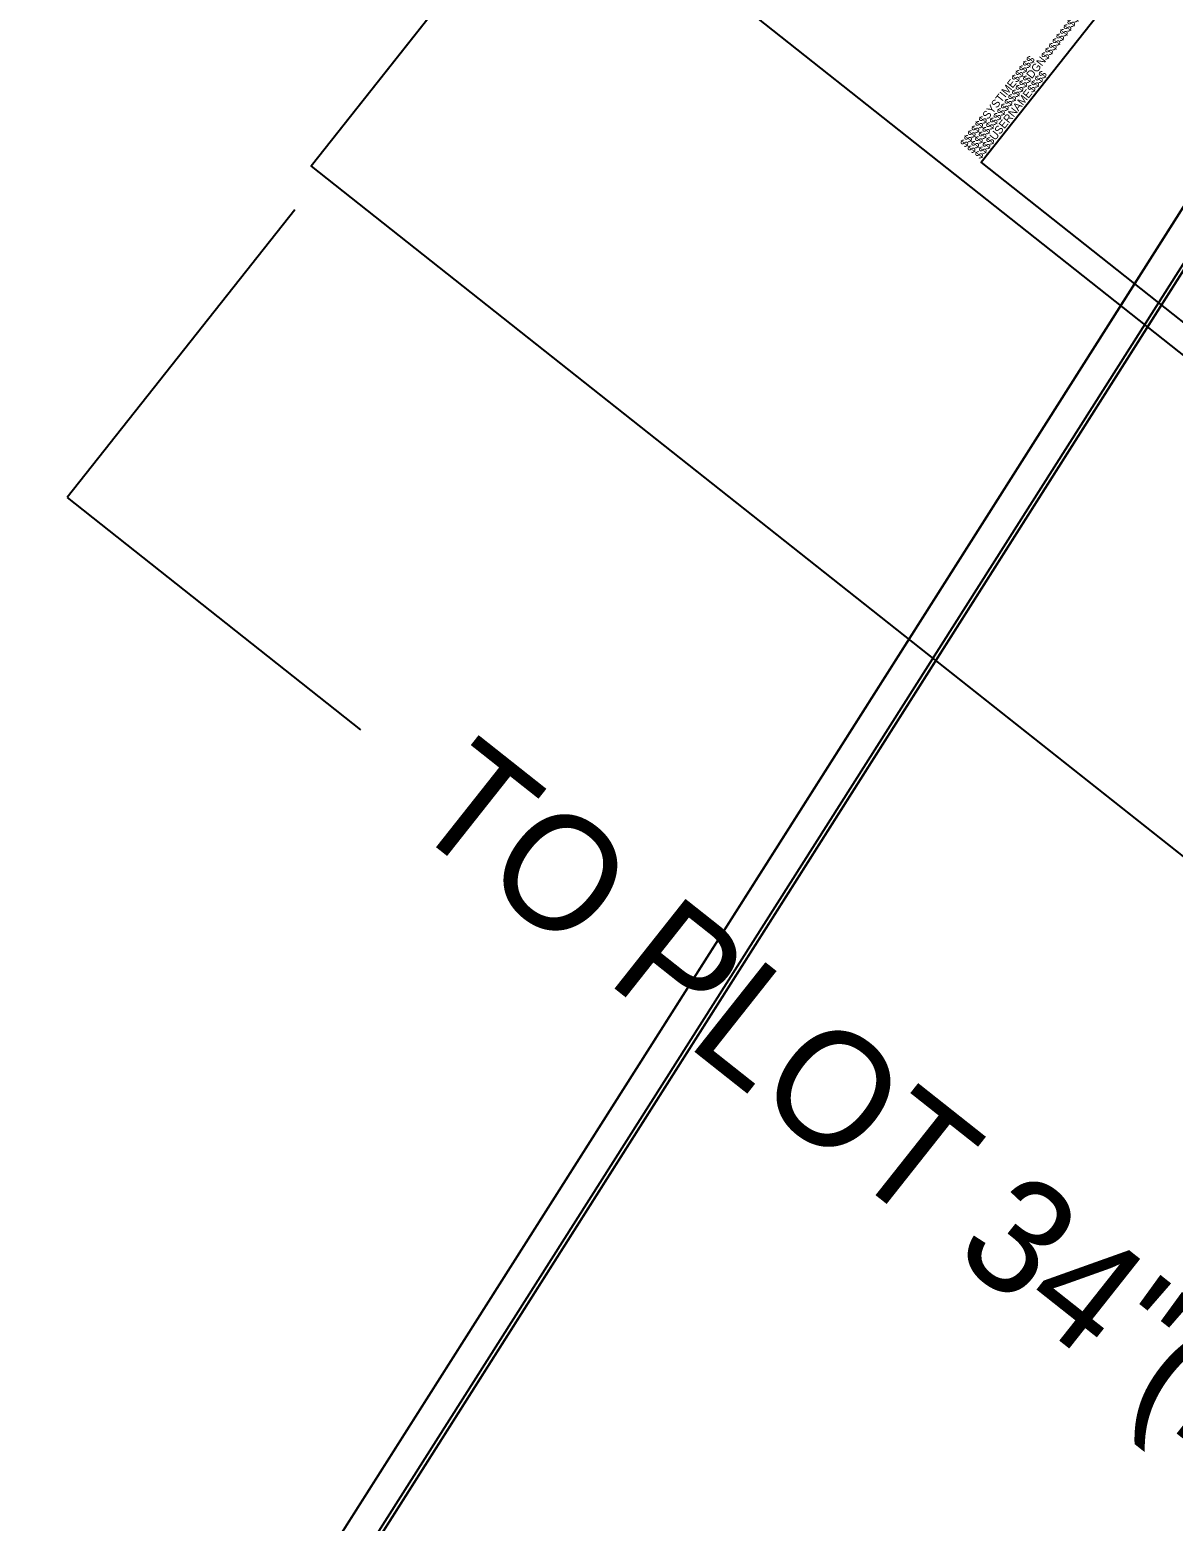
# Model space of a CAD drawing. Extents: x 1778994 to 1784559, y 810461 to 816654.
# Drawn here: x 1780200 to 1780950, y 812239 to 813217 of the extents above; entities that cross this region are included whole.
import ezdxf

# ---------------------------------------------------------------- set-up
doc = ezdxf.new("R2010")
doc.units = 0
for name, color, linetype in [('Sheet Clip Boundary CELL', 7, 'Continuous'), ('Sheet Cutting Line CELL', 7, 'Continuous'), ('Sheet Detail CELL', 7, 'Continuous'), ('Sheet Layout Plan Border', 7, 'Continuous'), ('Sheet Plan CELL', 7, 'Continuous'), ('Sheet Plan Layout CELL', 7, 'Continuous'), ('Sheet Plot Border Inside CELL', 7, 'Continuous'), ('Sheet Plot Border Outside CELL', 7, 'Continuous')]:
    doc.layers.add(name, color=color, linetype=linetype)

msp = doc.modelspace()

# ---------------------------------------------------------------- linework, layer by layer
at = {"layer": 'Sheet Clip Boundary CELL'}
msp.add_lwpolyline([(1781004.66, 813135.18), (1780254.51, 811953.1), (1780962.49, 811503.81), (1781063.9, 811663.61), (1781242.47, 811550.29), (1781891.21, 812572.57)], close=True, dxfattribs=at)
at = {"layer": 'Sheet Cutting Line CELL'}
for p, q in [((1781749.66, 814852.38), (1780384.09, 813127.55)), ((1781101.65, 813330.03), (1780199.6, 811908.59)), ((1780384.09, 813127.55), (1783024.7, 811036.95))]:
    msp.add_line(p, q, dxfattribs=at)
at = {"layer": 'Sheet Detail CELL'}
for p, q in [((1780373.43, 813098.94), (1780223.99, 812910.19)), ((1780223.99, 812910.19), (1780416.55, 812757.74))]:
    msp.add_line(p, q, dxfattribs=at)
msp.add_lwpolyline([(1781847.91, 814423.9), (1784200, 812561.73), (1783175.8, 811268.08), (1780823.71, 813130.25)], close=True, dxfattribs=at)
msp.add_lwpolyline([(1780853.12, 813106.97), (1780853.12, 813106.97)], dxfattribs=at)
at = {"layer": 'Sheet Layout Plan Border'}
msp.add_lwpolyline([(1781004.66, 813135.18), (1780254.51, 811953.1), (1780962.49, 811503.81), (1781063.9, 811663.61), (1781242.47, 811550.29), (1781891.21, 812572.57)], close=True, dxfattribs=at)
at = {"layer": 'Sheet Plan CELL'}
for points in [[(1781114.25, 811348.25), (1781918, 812614.78), (1781031.45, 813177.39), (1780227.72, 811910.89)], [(1781031.45, 813177.39), (1781917.99, 812614.82), (1781221.47, 811517.18), (1781094.76, 811597.57), (1780987.56, 811428.68), (1780227.72, 811910.89)]]:
    msp.add_lwpolyline(points, close=True, dxfattribs=at)
at = {"layer": 'Sheet Plan Layout CELL'}
msp.add_lwpolyline([(1781917.99, 812614.82), (1781031.45, 813177.39), (1780227.72, 811910.9), (1780935.71, 811461.6), (1781063.9, 811663.61), (1781242.47, 811550.29)], close=True, dxfattribs=at)
at = {"layer": 'Sheet Plot Border Inside CELL'}
for points in [[(1784230.15, 812559.54), (1781642.85, 814607.93), (1780597.55, 813287.62), (1783184.85, 811239.23)], [(1781111.57, 813308.33), (1780218.91, 811901.68), (1781109.67, 811336.39), (1782002.34, 812743.04)]]:
    msp.add_lwpolyline(points, close=True, dxfattribs=at)
at = {"layer": 'Sheet Plot Border Outside CELL'}
for points in [[(1784390.27, 812761.78), (1781749.66, 814852.38), (1780384.09, 813127.55), (1783024.7, 811036.95)], [(1781101.65, 813330.03), (1780199.6, 811908.59), (1781124.14, 811321.87), (1782026.2, 812743.3)]]:
    msp.add_lwpolyline(points, close=True, dxfattribs=at)

# ---------------------------------------------------------------- texts
at = {"layer": 'Sheet Detail CELL'}
for s, height, rotation, p in [('$$$$$$$$$$$$$$$$DGN$$$$$$$$$$$$$$$$', 5.25, 51.63093, (1780818.25, 813135.6)), ('$$$$$$SYSTIME$$$$$', 5.25, 51.63093, (1780813.59, 813139.54)), ('$$$$USERNAME$$$$', 5.25, 51.63093, (1780823.24, 813131.9)), ('TO PLOT 34"(HALF SIZE)', 75, 321.63093, (1780445.73, 812696.88))]:
    msp.add_text(s, height=height, rotation=rotation, dxfattribs=at).set_placement(p)

doc.saveas('drawing.dxf')
